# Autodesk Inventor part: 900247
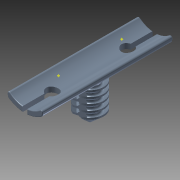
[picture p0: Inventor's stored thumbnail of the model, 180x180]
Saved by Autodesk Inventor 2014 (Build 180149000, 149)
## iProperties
Created: 2007-12
Part Number: 900247
Document SubType Name: Modeling
Designer: DV
Density: 1.13 g/cm^3
Material: Nylon Composite (Nylon, molybdenum disulphide)
Description: WIRE MOUNTING TAB - STRAIGHT
Mass: 0.768729 g
Surface Area: 12.6483 cm^2
Volume: 0.680291 cm^3
Appearance: Steel Blue
Component Category: Electrical
Author: DV
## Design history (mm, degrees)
sketch "Sketch1"
  geometry: L1 (-3.75, 1.605)-(-3.75, 2.068); L2 (-2.12, 1.835)-(-2.12, 2.144); L3 (-2.782, 2.446)-(-3.75, 1.605); L4 (-3.75, 3.255)-(-3.75, 3.718); L5 (-3.75, 2.068)-(-2.12, 3.485); L6 (-2.782, 4.096)-(-3.75, 3.255); L7 (-2.12, 3.485)-(-2.12, 3.794); L8 (-3.75, 3.718)-(-2.12, 5.135); L9 (-3.75, 4.905)-(-3.75, 5.368); L10 (-2.12, 5.135)-(-2.12, 5.444); L11 (-2.782, 5.746)-(-3.75, 4.905); L12 (-3.75, 5.368)-(-2.12, 6.785); L13 (-3.75, 6.555)-(-3.75, 7.019); L14 (-2.12, 6.785)-(-2.12, 7.094); L15 (-2.782, 7.396)-(-3.75, 6.555); L16 (-3.75, 7.019)-(0, 10.278); L17 (-3.75, 0.418)-(-2.12, 1.835); L18 (-2.12, 0)-(-2.12, 0.494); L19 (-2.9, 0)-(-2.12, 0); L20 (-2.782, 0.796)-(-3.75, -0.045); L21 (-3.75, -0.045)-(-3.75, 0.418); L22 (-2.9, -1.359)-(-2.9, 0); L23 (-4.465, -2.205)-(-4.85, -2.473); L24 (-4.85, -2.473)-(-4.85, -4.314); L25 (-4.111, -3.695)-(-4.85, -4.314); L26 (4.111, -3.695)-(4.85, -4.314); L27 (4.85, -2.473)-(4.85, -4.314); L28 (0, -0.8)-(0, 10.278); A1 r 0.4 centre (-2.52, 2.144) between (-2.12, 2.144) and (-2.782, 2.446); A2 r 6.4 centre (0, -8.6) between (4.111, -3.695) and (-4.111, -3.695); A3 r 0.4 centre (-2.52, 5.444) between (-2.12, 5.444) and (-2.782, 5.746); A4 r 0.4 centre (-2.52, 7.094) between (-2.12, 7.094) and (-2.782, 7.396); A5 r 0.4 centre (-2.52, 3.794) between (-2.12, 3.794) and (-2.782, 4.096); A6 r 0.4 centre (-2.52, 0.494) between (-2.12, 0.494) and (-2.782, 0.796); A7 r 7.8 centre (0, -8.6) between (4.85, -2.491) and (-4.465, -2.205); 2 further points
  constraints: 56 end point, 17 point on circle, 12 tangent, 11 parallel, 8 collinear, 7 centre point, 3 horizontal alignment, 2 vertical, 2 vertical alignment, 1 horizontal, 1 point on line
  dimensions: "d2" = 9.7 distance between parallel lines of L27 L24; "d3" = 1.84109 distance of L23.end L24.end; "d4" = 6.4 radius of A2; "d6" = 4.85 distance from line of L24 point (0, 0); "d7" = 0.8 distance of point (0, 0) L28.start; "d8" = 2.2 distance of point (0, -2.2) point (0, 0); "d9" = 4.31429 vertical distance of L26.end point (0, 0); "d10" = 2.49119 vertical distance of point (0, 0) A7.start; "d11" = 7.8 radius of A7; "d12" = 3.75 distance between parallel lines of L28 L13; "d13" = 2.12 distance between parallel lines of L28 L14; "d14" = 2.52 distance from line of L28 A4.centre; "d15" = 0.4 radius of A4; "d16" = 3.18436 vertical distance of L16.end A4.centre; "d17" = 49 deg angle of L28 L16; "d18" = 0.4 radius of A3 (= d15); "d19" = 0.4 radius of A5 (= d15); "d20" = 0.4 radius of A1 (= d15); "d21" = 0.4 radius of A6 (= d15); "d22" = 0.30908 distance of L12.end L14.end; "d23" = 0.30908 distance of L8.end L10.end (= d22); "d24" = 0.30908 distance of L5.end L7.end (= d22); "d25" = 0.30908 distance of L2.start L2.end (= d22); "d26" = 0.49397 distance of L18.start L18.end; "d27" = 0.4632 distance of L20.end L17.start; "d28" = 0.4632 distance of L1.start L1.end (= d27); "d29" = 0.4632 distance of L4.start L4.end (= d27); "d30" = 0.4632 distance of L9.start L9.end (= d27); "d31" = 2.9 distance from line of L28.start L22
extrude "Extrusion1" new body sketch "Sketch1" stored distance "d32" = 36; taper "d33" = 0 deg
revolve "Revolution1" stored, may be unused: angle "d34" = 90 deg
fillet "Fillet1" dims "d35" = 0.7
fillet "Fillet2" dims "d36" = 0.45
fillet "Fillet3" dims "d37" = 0.9
fillet "Fillet4" dims "d38" = 0.2
workplane "Work Plane1"
sketch "Sketch2"
  geometry: L1 (-1.2, 1.947)-(1.2, 1.947); L2 (-1.2, -1.947)-(1.2, -1.947); L3 (1.2, 3.553)-(1.2, 1.947); L4 (1.2, -1.947)-(1.2, -3.553); L5 (-1.2, -3.553)-(-1.2, -1.947); L6 (-1.2, 1.947)-(-1.2, 3.553); A1 r 3.75 centre (0, 0) between (-1.2, 3.553) and (1.2, 3.553) reference; 3 further points
  constraints: 12 end point, 4 parallel, 4 perpendicular, 4 point on circle, 2 collinear, 2 midpoint, 2 vertical alignment
  dimensions: "d40" = 1.803 distance edge to line of A1 L1; "d41" = 1.803 distance edge to line of A1 L2 (= d40); "d42" = 2.4 distance of L1.start L1.end
extrude "Extrusion2" cut sketch "Sketch2" distance "d43" = 10.8; taper "d44" = 0 deg
sketch "Sketch3"
  geometry: L1 (-4.351, 18)-(4.351, 18) reference; L2 (4.351, -18)-(-4.351, -18) reference; L3 (-0.665, 18)-(0.665, 18); L4 (0.665, 18)-(0.665, 11.91); L5 (-0.665, 11.91)-(-0.665, 18); L6 (0, 18)-(0, 0); L7 (-0.665, -18)-(0.665, -18); L8 (0.665, -18)-(0.665, -11.91); L9 (-0.665, -11.91)-(-0.665, -18); A1 r 1.65 centre (0, 10.4) between (-0.665, 11.91) and (0.665, 11.91); A2 r 1.65 centre (0, -10.4) between (0.665, -11.91) and (-0.665, -11.91)
  constraints: 14 end point, 4 point on circle, 3 parallel, 2 centre point, 2 collinear, 2 horizontal, 2 perpendicular, 2 point on line, 2 vertical alignment, 1 equal radius, 1 midpoint
  dimensions: "d45" = 1.65 radius of A1; "d46" = 1.33 distance between parallel lines of L5 L4; "d47" = 7.6 distance from line of A1.centre L1; "d48" = 7.6 distance from line of L2 A2.centre (= d47)
extrude "Extrusion3" cut sketch "Sketch3" stored distance "d49" = 10.8; taper "d50" = 0 deg
workpoint "Work Point1"
workpoint "Work Point2"
body "Solid1"
other parameters: "d39" = 10.75, "d51" = 0
